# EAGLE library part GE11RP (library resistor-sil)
SIL RESISTOR
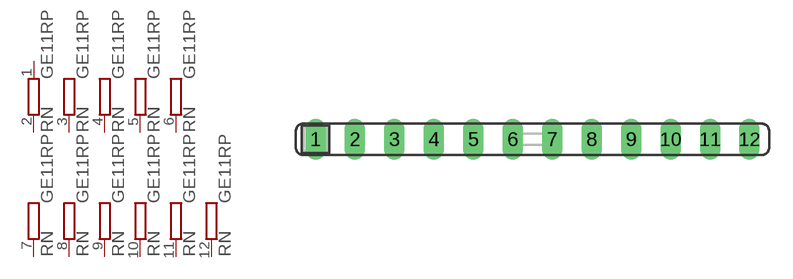
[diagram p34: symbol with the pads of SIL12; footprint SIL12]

Designator prefix RN; gates A=R-PV B=R-PV1 C=R-PV1 D=R-PV1 E=R-PV1 F=R-PV1 G=R-PV1 H=R-PV1 I=R-PV1 J=R-PV1 K=R-PV1

## GE11RP (OC_FARNELL: unknown; OC_NEWARK: unknown)  [SIL12]
1  A:1  pas
2  A:2  pas
3  B:2  pas
4  C:2  pas
5  D:2  pas
6  E:2  pas
7  F:2  pas
8  G:2  pas
9  H:2  pas
10  I:2  pas
11  J:2  pas
12  K:2  pas

## Footprint SIL12 (pad centres in mm)
Single In Line
drill 0.813 long: 1 -13.97,0; 2 -11.43,0; 3 -8.89,0; 4 -6.35,0; 5 -3.81,0; 6 -1.27,0; 7 1.27,0; 8 3.81,0; 9 6.35,0; 10 8.89,0; 11 11.43,0; 12 13.97,0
